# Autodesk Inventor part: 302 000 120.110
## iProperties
Created: 2007-08
Part Number: 302 000 120.110
Material: 1.0401 C15 (Einsatzst.)
Description: Gewindeeinstatz für Metal ENSAT-S M12
Document SubType Name: Modellieren
Designer: TMT
Manufacturer: Standard
Standards Organization: Custom
Mass: 25.3392 g
Surface Area: 25.4262 cm^2
Volume: 3.23204 cm^3
Density: 7.84 g/cm^3
Vendor: Kerb Konus
Author: TMT
Comments: Kerb Konus
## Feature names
1. Extrusion2
2. Bohrung1 [Hole]
3. Extrusion3
